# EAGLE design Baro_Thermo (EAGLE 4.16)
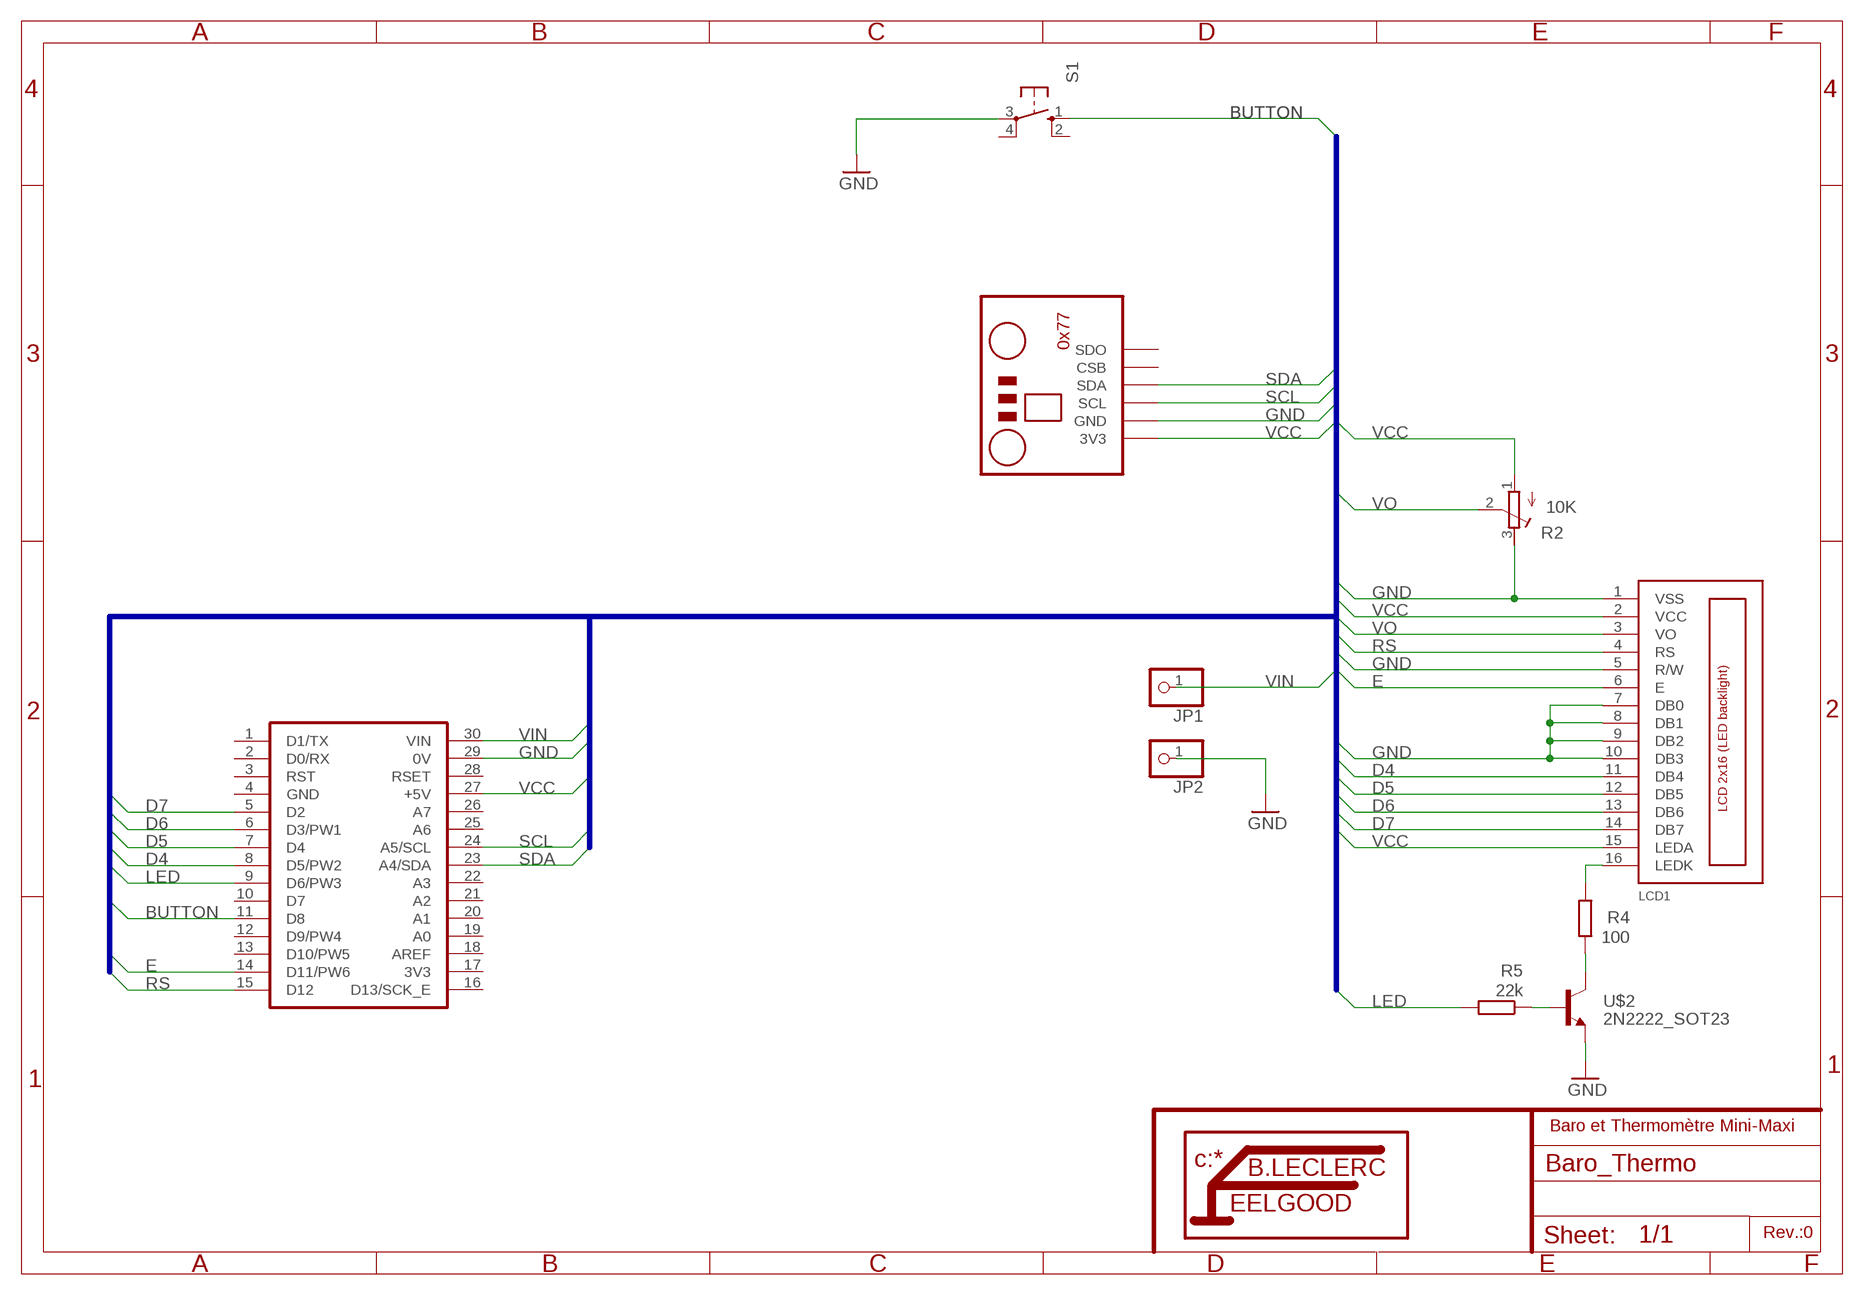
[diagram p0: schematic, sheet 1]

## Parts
JP1  PINHD-1X1  [1X01]
JP2  PINHD-1X1  [1X01]
LCD1  LCD_2X16_SIL  [HY-1602F]
R2  10K  R-TRIMM3103  [RTRIM3103]
R4  100  R-EU_M1206  [M1206]
R5  22k  R-EU_M1206  [M1206]
S1  10-XX  [B3F-10XX]
U1  NANO  [NANO]
U$2  2N2222_SOT23  [SOT23-BEC]
U$3  BMP280  [BMP280]

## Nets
BUTTON: S1.1(S) U1.11(D8)
D4: LCD1.11(DB4) U1.8(D5/PW2)
D5: LCD1.12(DB5) U1.7(D4)
D6: LCD1.13(DB6) U1.6(D3/PW1)
D7: LCD1.14(DB7) U1.5(D2)
E: LCD1.6(E) U1.14(D11/PW6)
GND: JP2.1 LCD1.1(VSS) LCD1.5(R/W) LCD1.7(DB0) LCD1.8(DB1) LCD1.9(DB2) LCD1.10(DB3) R2.3(A) S1.3(P) U1.29(0V) U$2.E U$3.GND
LED: R5.2 U1.9(D6/PW3)
N$3: LCD1.16(LEDK) R4.2
N$8: R4.1 U$2.C
N$9: R5.1 U$2.B
RS: LCD1.4(RS) U1.15(D12)
SCL: U1.24(A5/SCL) U$3.SCL
SDA: U1.23(A4/SDA) U$3.SDA
VCC: LCD1.2(VCC) LCD1.15(LEDA) R2.1(E) U1.27(+5V) U$3.3V3
VIN: JP1.1 U1.30(VIN)
VO: LCD1.3(VO) R2.2(S)
Unconnected: S1.2(S1) S1.4(P1) U1.1(D1/TX) U1.2(D0/RX) U1.3(RST) U1.10(D7) U1.12(D9/PW4) U1.13(D10/PW5) U1.16(D13/SCK_E) U1.18(AREF) U1.19(A0) U1.20(A1) U1.21(A2) U1.22(A3) U1.25(A6) U1.26(A7) U1.28(RSET) U$3.CSB U$3.SDO

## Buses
B$1

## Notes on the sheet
- Baro et Thermomètre Mini-Maxi
- Rev.:0

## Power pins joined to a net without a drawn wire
3V3: U1.17(3V3)
GND: U1.4(GND)

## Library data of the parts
JP1 JP2 = pinhead:PINHD-1X1: PIN HEADER
LCD1 = lcd_2x16_led_backlight:LCD_2X16_SIL
R2 = rcl:R-TRIMM: Trimm resistor
R4 R5 = rcl:R-EU_: RESISTOR, European symbol
S1 = switch-omron:10-XX: OMRON SWITCH
U1 = Arduino:NANO
U$2 = transistor:2N2222_SOT23
U$3 = Arduino:BMP280

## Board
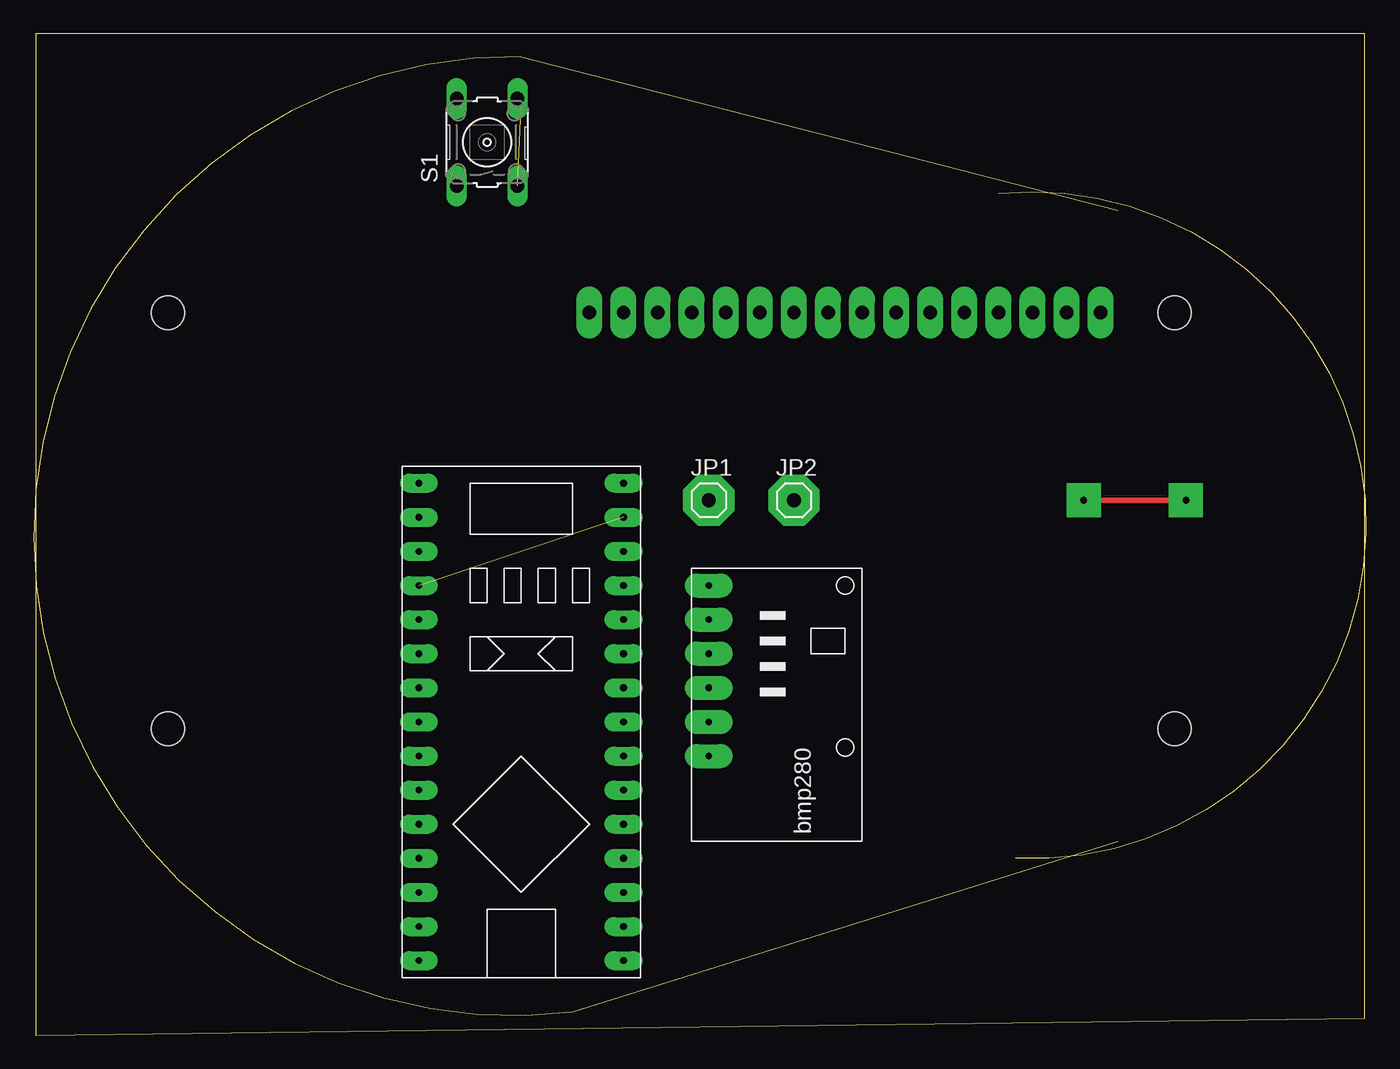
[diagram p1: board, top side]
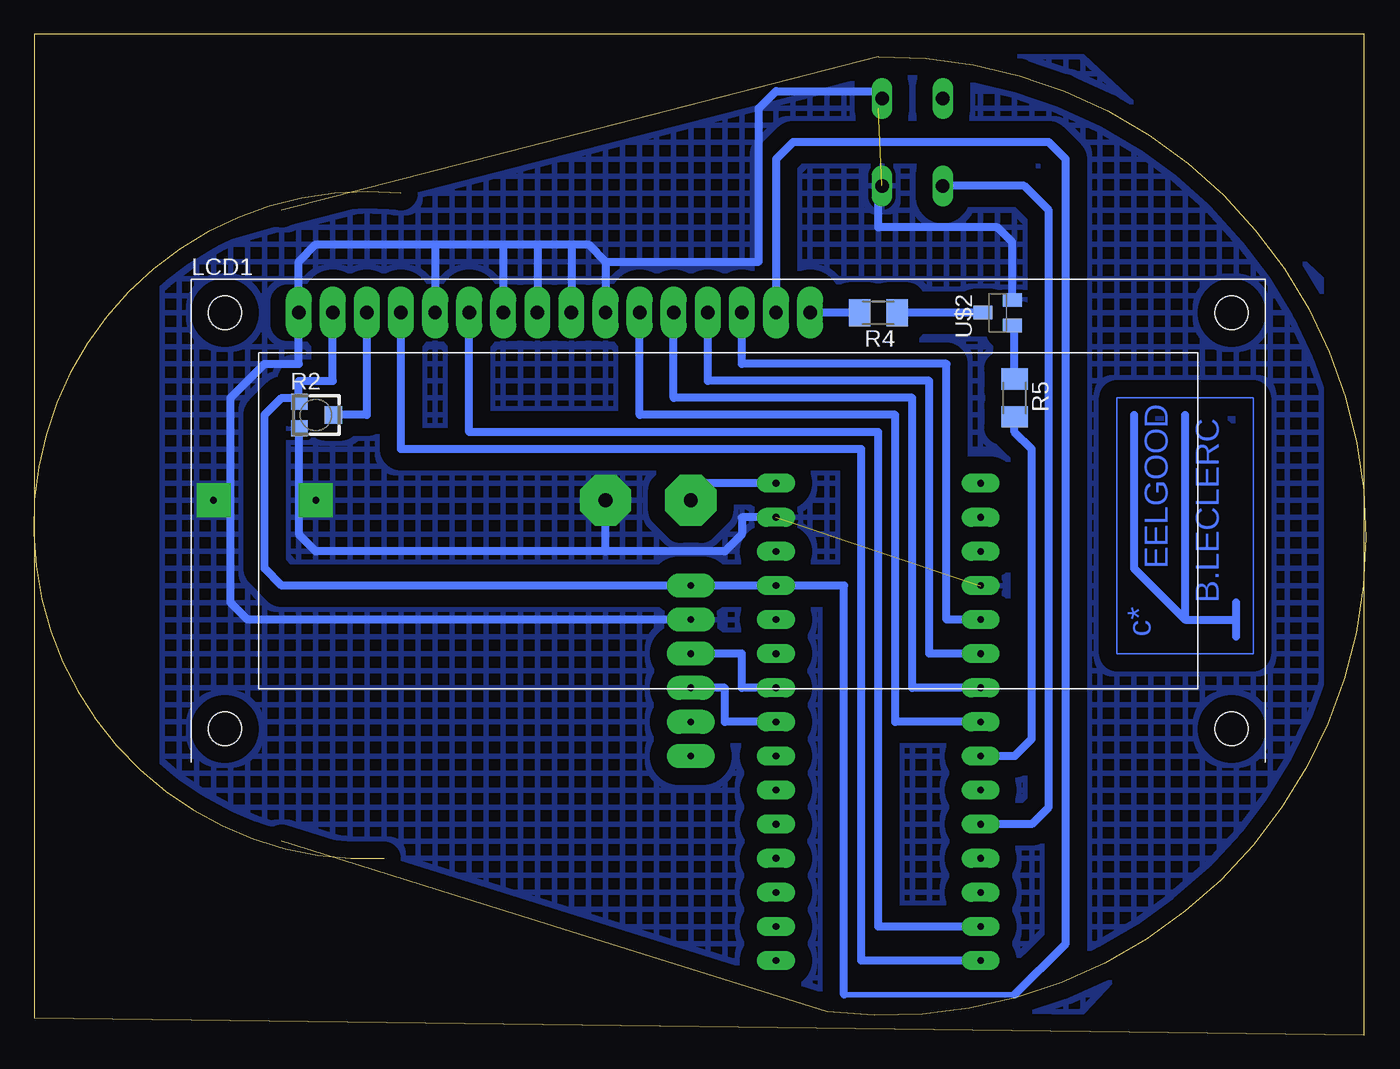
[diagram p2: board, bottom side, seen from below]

Size 99.28 x 74.6 mm. Coordinates in mm from the lower left corner, seen from the top.
Outline: 71.9,62.7 arc-189 73.17,13.17
Outline: 80.79,61.43 36.34,72.86 arc188 40.15,1.74 80.79,14.44
Outline: 0.15,0 99.19,1.27 99.19,74.6 0.15,74.6 0.15,0
Copper layers (1*16): Top 0.035mm / dielectric 1.5mm / Bottom 0.035mm
Design rules "default": minimum track width 10mil, minimum drill 24mil, track to track 8mil, track to pad 8mil, pad to pad 8mil, via to via 8mil, smd to smd 8mil, copper to edge 40mil, drill to drill 8mil, minimum pad ring 10mil, minimum via ring 8mil, stop-mask expansion 4mil, vias tented up to drill 0mil, thermal gap 10mil

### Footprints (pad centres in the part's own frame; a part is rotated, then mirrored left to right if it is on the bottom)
1X01 = drill 1.016 octagon: 1 0,0
HY-1602F = drill 1 pad 1.93 long: 1 2.54,0; 2 5.08,0; 3 7.62,0; 4 10.16,0; 5 12.7,0; 6 15.24,0; 7 17.78,0; 8 20.32,0; 9 22.86,0; 10 25.4,0; 11 27.94,0; 12 30.48,0; 13 33.02,0; 14 35.56,0; 15 38.1,0; 16 40.64,0 | hole 2.5: -2.96,0; 72.04,0; -2.96,-31; 72.04,-31
RTRIM3103 = smd 1.2 x 1.25: 1 -1,-1.225; 3 1,-1.225 | smd 1.3 x 1.3: 2 0,1.3
M1206 = smd 1.6 x 2: 1 -1.4,0; 2 1.4,0
B3F-10XX = drill 1.016 long: 1 -3.251,2.261; 2 3.251,2.261; 3 -3.251,-2.261; 4 3.251,-2.261
NANO = drill 0.5 pad 1.422 long: 1 -7.62,17.78; 2 -7.62,15.24; 3 -7.62,12.7; 4 -7.62,10.16; 5 -7.62,7.62; 6 -7.62,5.08; 7 -7.62,2.54; 8 -7.62,0; 9 -7.62,-2.54; 10 -7.62,-5.08; 11 -7.62,-7.62; 12 -7.62,-10.16; 13 -7.62,-12.7; 14 -7.62,-15.24; 15 -7.62,-17.78; 16 7.62,-17.78; 17 7.62,-15.24; 18 7.62,-12.7; 19 7.62,-10.16; 20 7.62,-7.62; 21 7.62,-5.08; 22 7.62,-2.54; 23 7.62,0; 24 7.62,2.54; 25 7.62,5.08; 26 7.62,7.62; 27 7.62,10.16; 28 7.62,12.7; 29 7.62,15.24; 30 7.62,17.78
SOT23-BEC = smd 1 x 1.4: B -0.95,-1.1; C 0,1.1; E 0.95,-1.1
BMP280 = drill 0.5 pad 1.778 long: 3V3 -6.35,-7.62; CSB 3.81,-7.62; GND -3.81,-7.62; SCL -1.27,-7.62; SDA 1.27,-7.62; SDO 6.35,-7.62

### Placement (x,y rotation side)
JP1  50.31,39.84 0 top
JP2  56.66,39.84 0 top
LCD1  82.06,53.81 0 bottom
R2  78.25,46.19 270 bottom
R4  36.34,53.81 180 bottom
R5  26.18,47.46 270 bottom
S1  33.8,66.51 90 top
U1  36.34,23.33 0 top
U$2  27.45,53.81 90 bottom
U$3  57.93,27.14 270 top
U$4  [LITTFEEL]  5.86,30.95 90 bottom

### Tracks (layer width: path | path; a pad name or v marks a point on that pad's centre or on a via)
BUTTON
  Bottom 0.61: S1.1 25.47,63.26 23.64,61.43 23.64,16.98 24.91,15.71 U1.11
D4
  Bottom 0.61: LCD1.11 54.12,46.19 35.07,46.19 35.07,23.33 U1.8
D5
  Bottom 0.61: U1.7 33.8,25.87 33.8,47.46 51.58,47.46 LCD1.12
D6
  Bottom 0.61: LCD1.13 49.04,48.73 32.53,48.73 32.53,28.41 U1.6
D7
  Bottom 0.61: U1.5 31.26,30.95 31.26,50 46.5,50 LCD1.14
E
  Bottom 0.61: LCD1.6 66.82,44.92 36.34,44.92 36.34,8.09 U1.14
GND  (via drill 0.5 pad 2.54, 0.5 pad 3.81)  (2 unrouted)
  Top 0.406: v78.25,39.84 v85.87,39.84
  Bottom 0.61: 56.66,57.62 LCD1.10 | 56.66,57.62 57.93,58.89 59.2,58.89 | 61.74,58.89 59.2,58.89 | 64.28,58.89 61.74,58.89 | 59.2,58.89 LCD1.9 | 61.74,58.89 LCD1.8 | 64.28,58.89 LCD1.7 | 69.36,58.89 LCD1.5 | 69.36,58.89 64.28,58.89 | 69.36,58.89 78.25,58.89 79.52,57.62 LCD1.1 79.52,50 82.06,50 84.6,47.46 84.6,32.22 83.33,30.95 U$3.GND | R2.3 79.47,37.26 78.25,36.03 56.66,36.03 | 56.66,36.03 47.77,36.03 46.5,37.3 46.5,38.57 U1.29 | U$2.E 26.35,59.06 27.45,60.16 36.34,60.16 36.34,62.7 | 56.66,57.62 45.23,57.62 45.23,69.05 43.96,70.32 36.34,70.32 36.34,69.05 | 56.66,36.03 JP2.1
  other vias: 56.66,39.84
  pour Bottom (isolate 1.27, hatched): 36.34,72.86 89.68,57.62 89.68,18.25 36.34,1.74 21.1,1.74 3.32,20.79 3.32,56.35 21.1,72.86
LED
  Bottom 0.61: R5.2 26.18,44.92 24.91,43.65 24.91,22.06 26.18,20.79 U1.9
N$1  (via drill 0.5 pad 1.68)
  other vias: 59.2,53.81
N$2  (via drill 0.5 pad 1.68)
  other vias: 49.04,53.81
N$3
  Bottom 0.61: R4.2 LCD1.16
N$4  (via drill 0.5 pad 1.68)
  other vias: 76.98,53.81
N$5  (via drill 0.5 pad 1.68)
  other vias: 56.66,53.81
N$6  (via drill 0.5 pad 1.68)
  other vias: 74.44,53.81
N$7  (via drill 0.5 pad 1.68)
  other vias: 66.82,53.81
N$8
  Bottom 0.61: 35.07,53.81 R4.1 U$2.C
N$9
  Bottom 0.61: U$2.B 26.35,52.71 26.18,52.54 R5.1
N$10  (via drill 0.5 pad 1.68)
  other vias: 79.52,53.81
N$11  (via drill 0.5 pad 1.68)
  other vias: 71.9,53.81
N$12  (via drill 0.5 pad 1.68)
  other vias: 69.36,53.81
N$13  (via drill 0.5 pad 1.68)
  other vias: 64.28,53.81
N$14  (via drill 0.5 pad 1.68)
  other vias: 61.74,53.81
N$15  (via drill 0.5 pad 1.68)
  other vias: 54.12,53.81
N$16  (via drill 0.5 pad 1.68)
  other vias: 51.58,53.81
N$17  (via drill 0.5 pad 1.68)
  other vias: 46.5,53.81
N$18  (via drill 0.5 pad 1.68)
  other vias: 43.96,53.81
N$19  (via drill 0.5 pad 1.68)
  other vias: 41.42,53.81
N$20  (via drill 0.5 pad 3.81)
  other vias: 50.31,39.84
RS
  Bottom 0.61: U1.15 37.61,5.55 37.61,43.65 71.9,43.65 LCD1.4
SCL
  Bottom 0.61: U$3.SCL 46.5,28.41 46.5,25.87 U1.24
SDA
  Bottom 0.61: U$3.SDA 47.77,25.87 47.77,23.33 U1.23
VCC
  Bottom 0.406: 26.18,3.01 38.88,3.01
  Bottom 0.61: LCD1.2 76.98,48.73 79.52,48.73 79.52,47.46 | 79.52,47.46 79.47,47.41 R2.1 | 79.52,47.46 80.79,47.46 82.06,46.19 82.06,34.76 80.79,33.49 U$3.3V3 U1.27 38.88,33.49 38.88,3.01 | LCD1.15 43.96,65.24 42.69,66.51 23.64,66.51 22.37,65.24 22.37,6.82 26.18,3.01
VIN
  Bottom 0.61: JP1.1 49.04,41.11 U1.30
VO
  Bottom 0.61: LCD1.3 74.44,46.19 R2.2 76.98,46.19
